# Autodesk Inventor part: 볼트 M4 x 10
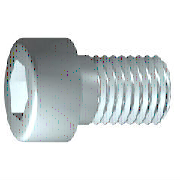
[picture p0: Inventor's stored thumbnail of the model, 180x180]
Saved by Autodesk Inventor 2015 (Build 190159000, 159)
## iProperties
IsCustomPart: 0
Created: 2012-02
Part Number: 볼트 M4 x 10
Material: 스테인리스강
Description: 6각 소켓 머리 캡 나사
Document SubType Name: Modeling
Standard: ISO 4762
Designer: mduedu
Standard Revision: Fourth edition 2004-03-01
Standards Organization: ISO
Language: ko-KR
Size Designation: M4 x 10
Categories: <MemberInstance><Categories><Category DisplayName="조임쇠" InternalName="e4da775c-781d-43d5-af7c-5136215cf5a6" Mnemonic="FSTN"><Category DisplayName="볼트" InternalN
Density: 8.08 g/cm^3
Appearance: 반광택
Author: mduedu
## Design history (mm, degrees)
sketch "스케치1"
  geometry: L1 (-1, 0)-(10, 0); L2 (10, 0)-(10, 2); L3 (10, 2)-(1.75, 2); L4 (1.75, 2)-(1.32, 2); L5 (1.32, 2)-(0, 2); L6 (0, 2)-(0, 3.5); L7 (0, 3.5)-(-4, 3.5); L8 (-4, 3.5)-(-4, 1.732); L9 (-4, 1.732)-(-2, 1.732); L10 (-2, 1.732)-(-1, 0); L11 (-6.8, 0)-(12.8, 0) reference; L12 (0, -0.7)-(0, 4.2) reference; L13 (1.75, 2)-(0, 2)
  constraints: 22 end point, 6 parallel, 2 collinear, 2 perpendicular, 1 horizontal, 1 point on line
  dimensions: "d1" = 8.25 distance from line of L3.end L2 (= GEL); "d2" = 0.42952 distance of L4.end L3.end (computed from GAL); "d3" = 4 distance between parallel lines of L8 L6 (= KOH); "d4" = 2 distance of L8.end L9.end (= INTI); "d5" = 60 deg angle of L10 L1; "d6" = 4 diameter of L3 L1 (= GD); "d7" = 4 diameter of L5 L1 (= BDM); "d8" = 3.4641 diameter of L9 L1 (= 1.1547 x SW); "d9" = 7 diameter of L7 L1 (= KOD); "d26" = 10 distance between parallel lines of L12 L2 (= NLG)
revolve "본체" sketch "스케치1" stored, may be unused: angle "d10" = 90 deg
sketch "스케치2"
  geometry: L1 (0, -4.9)-(0, 4.9) reference; L2 (-4.9, 0)-(4.9, 0) reference; L3 (1.732, 0)-(0.866, -1.5); L4 (0.866, -1.5)-(-0.866, -1.5); L5 (-0.866, -1.5)-(-1.732, 0); L6 (-1.732, 0)-(-0.866, 1.5); L7 (-0.866, 1.5)-(0.866, 1.5); L8 (0.866, 1.5)-(1.732, 0); 2 further points
  constraints: 12 end point, 1 coincident, 1 horizontal alignment, 1 point on line, 12 other
extrude "슬롯" join sketch "스케치2" stored distance "d11" = 10; taper "d12" = 0 deg
workplane "Work Plane1"
fillet "Fillet2" dims "d30" = 0.1 (= R)
body "Solid1"
fillet "모깎기1" dims "d17" = 0.4 (= RR)
feature "스레드" dims "d13" = 8.25 (= GEL), "d14" = 0
chamfer "모따기1" distance "d15" = 0.42941 (= -0.5 x SPD + 0.5 x GD); stored, may be unused: second distance "d16" = 0.42941 (= GUL), angle "d27" = 45 deg
other parameters: "GD" = 4 [user parameter; used in 2 equation terms], "NLG" = 10 [user parameter; used in 1 equation term], "GEL" = 8.25 [user parameter; used in 2 equation terms], "KOD" = 7 [user parameter; used in 1 equation term], "KOH" = 4 [user parameter; used in 1 equation term], "INTI" = 2 [user parameter; used in 1 equation term], "GAL" = 0.42941 (= 0.61345 x PTC) [user parameter; used in 1 equation term], "GUL" = 0.42941 (= 0.61345 x PTC) [user parameter; used in 1 equation term], "BDM" = 4 (= NND) [user parameter; used in 1 equation term], "SW" = 3 [user parameter; used in 2 equation terms], "RR" = 0.4 [user parameter; used in 1 equation term], "SPD" = 3.14117 (= NND - 1.2269 x PTC) [user parameter; used in 1 equation term], "d19" = 0, "d28" = 0, "d29" = 0, "R" = 0.1 [user parameter; used in 1 equation term], "TOA" = 30 deg [user parameter], "GD1" = 3.14117 (= THREADDIA - 1.2269 x PTC) [user parameter], "THREADDIA" = 4 [user parameter; used in 1 equation term], "FAWI" = 45 deg [user parameter], "TPU" = 14.28571 (computed from PTC) [user parameter], "PTC" = 0.7 [user parameter; used in 5 equation terms], "NND" = 4 [user parameter; used in 2 equation terms], "E0" = 3.465 (= 1.155 x SW) [user parameter]
